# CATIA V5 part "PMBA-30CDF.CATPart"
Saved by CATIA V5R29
Part number: PMBA-30CDF
Definition: design
Source: Unknown
Bounding box of the stored display mesh (mm): x -31.731 to 38.27, y -19.657 to 50.843, z -37.112 to 22.889
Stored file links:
  C:\가치같이\SmartFactory_BoxErectorConveyor\PMBA-30CDF.CATPart
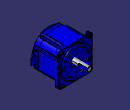
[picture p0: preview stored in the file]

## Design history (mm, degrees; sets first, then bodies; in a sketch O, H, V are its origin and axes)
Set1
  DatumSurface1 to DatumSurface376 "        "
Body1 (main body)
